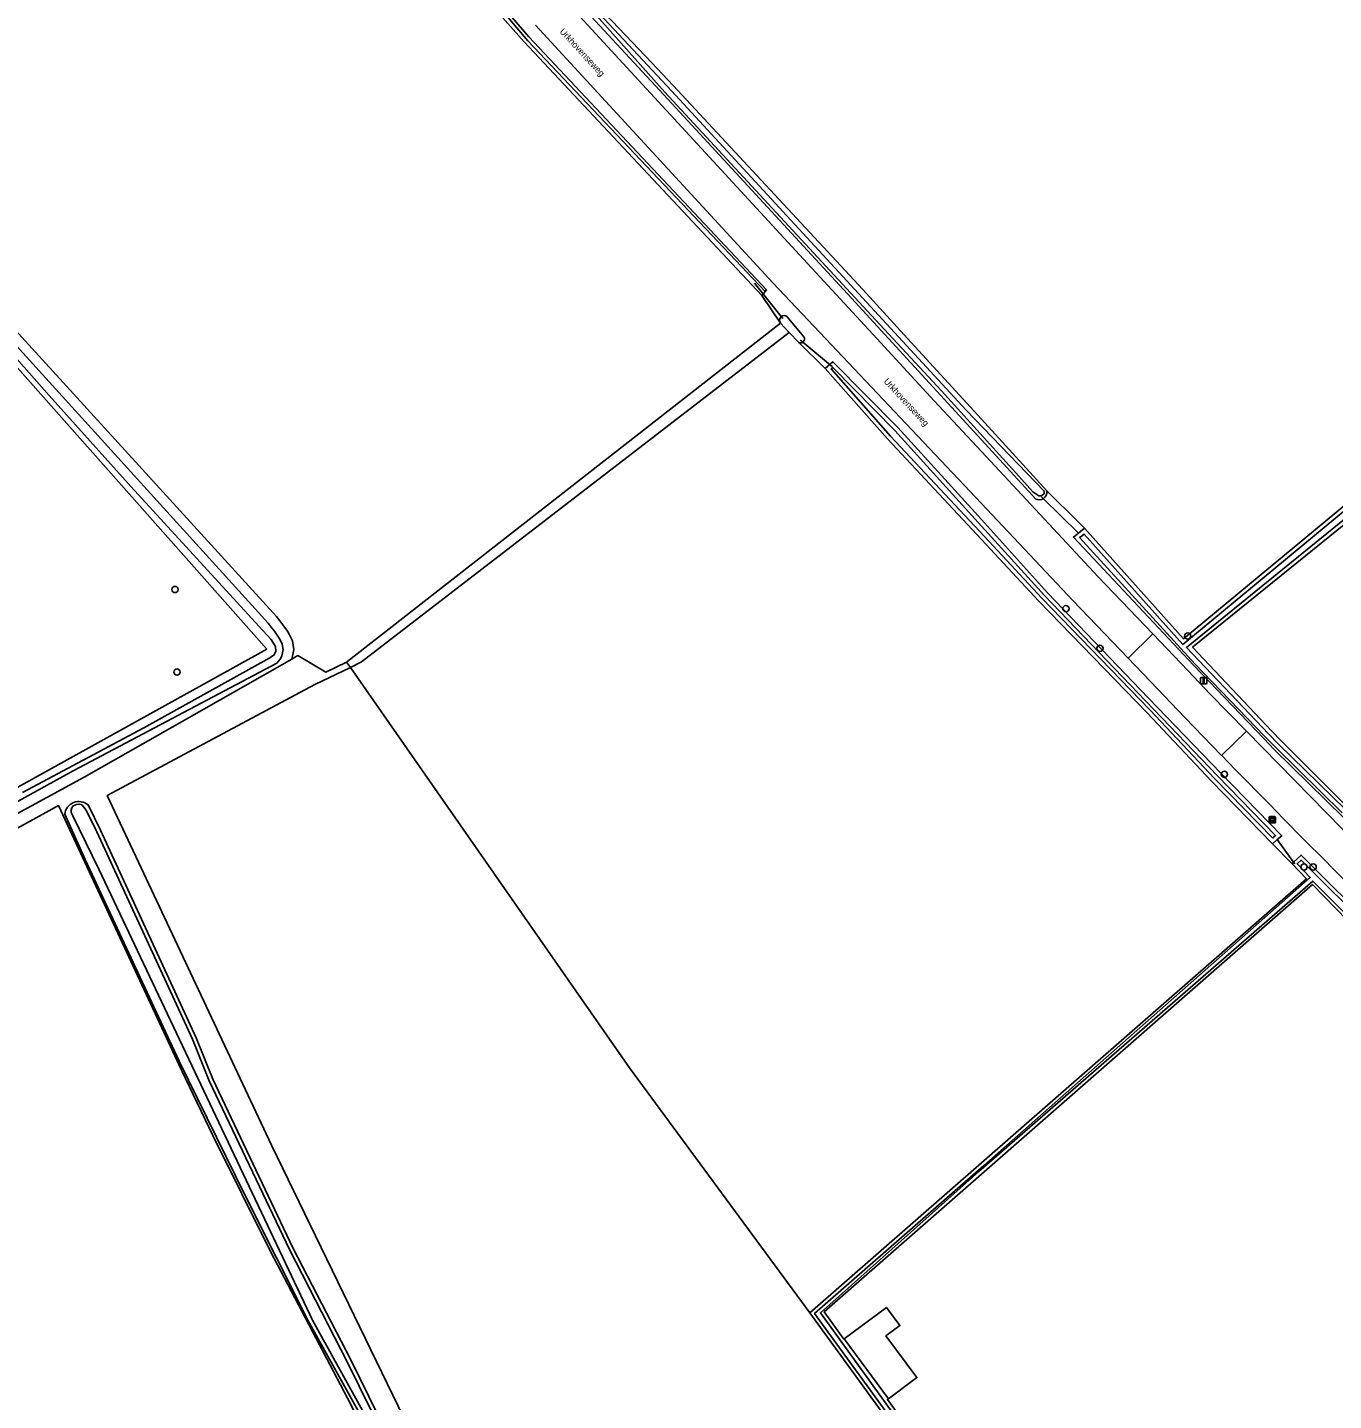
# Model space of a CAD drawing. Extents: x 164494 to 166241, y 382475 to 384495.
# Drawn here: x 165350.9 to 165555, y 382584 to 382798.6 of the extents above; entities that cross this region are included whole.
import ezdxf

# ---------------------------------------------------------------- set-up
doc = ezdxf.new("R2010")
doc.units = 0
for name, color, linetype in [('IMGEO_Boom', 7, 'Continuous'), ('IMGEO_Bouwland', 7, 'Continuous'), ('IMGEO_Duiker', 7, 'Continuous'), ('IMGEO_Erf', 7, 'Continuous'), ('IMGEO_Grasland_agrarisch', 7, 'Continuous'), ('IMGEO_Grasland_overig', 7, 'Continuous'), ('IMGEO_Groenvoorziening', 7, 'Continuous'), ('IMGEO_Hek', 7, 'Continuous'), ('IMGEO_Lichtmast', 7, 'Continuous'), ('IMGEO_Oever', 7, 'Continuous'), ('IMGEO_Openbare_ruimte_label', 7, 'Continuous'), ('IMGEO_Pand', 7, 'Continuous'), ('IMGEO_Rijbaan_lokaal_gesloten', 7, 'Continuous'), ('IMGEO_Rijbaan_lokaal_open', 7, 'Continuous'), ('IMGEO_Waterloop', 7, 'Continuous'), ('IMGEO_Wegwijzer', 7, 'Continuous')]:
    doc.layers.add(name, color=color, linetype=linetype)

msp = doc.modelspace()

# ---------------------------------------------------------------- linework, layer by layer
at = {"layer": 'IMGEO_Boom'}
for centre in [(165373.99, 382710.77), (165513.21, 382707.77), (165532.25, 382703.5), (165518.53, 382701.58), (165374.3, 382697.87), (165537.99, 382681.88), (165550.43, 382667.4), (165551.85, 382667.4)]:
    msp.add_circle(centre, 0.489, dxfattribs=at)
at = {"layer": 'IMGEO_Bouwland'}
msp.add_lwpolyline([(165439.25, 382802.82), (165448.48, 382793.1), (165451.85, 382789.55), (165481.46, 382757.64), (165488.44, 382750), (165500, 382737.37), (165510.24, 382726.17), (165515.2, 382721.28), (165516.13, 382720.35), (165531.58, 382703.08), (165565.88, 382731.47)], dxfattribs=at)
msp.add_lwpolyline([(165550.83, 382665.58), (165548.56, 382667.91), (165545.51, 382671.03), (165535.96, 382680.81), (165525.91, 382691.48), (165509, 382708.97), (165500, 382718.6), (165485.31, 382734.31), (165475.61, 382745.32), (165471.45, 382749.36), (165469.96, 382750.93), (165403.15, 382699.48), (165401.4, 382698.58), (165395.82, 382695.91), (165363.39, 382678.56), (165389.07, 382623.94), (165409.74, 382581.31), (165430.57, 382542.15), (165486.94, 382570.53), (165487.49, 382569.52), (165491.84, 382572.06), (165491.59, 382572.41), (165473.19, 382597.73), (165500, 382621.16)], close=True, dxfattribs=at)
at = {"layer": 'IMGEO_Duiker'}
for points in [[(165464.55, 382758.66), (165468.72, 382753.42), (165468.98, 382753.1)], [(165476.73, 382745.56), (165472.09, 382749.41), (165471.71, 382749.73)], [(165509.39, 382725.23), (165509.65, 382724.97), (165515.18, 382719.58)], [(165548.98, 382667.89), (165548.8, 382668.14), (165546.24, 382671.72)]]:
    msp.add_lwpolyline(points, dxfattribs=at)
at = {"layer": 'IMGEO_Erf'}
msp.add_lwpolyline([(165575.78, 382640.1), (165568.63, 382646.88), (165567.19, 382648.47), (165564.24, 382651.72), (165562.6, 382653.53), (165551.73, 382664.66), (165500, 382619.38), (165475.44, 382597.88), (165478.51, 382593.62), (165478.55, 382593.65), (165485.17, 382598.57), (165487.27, 382595.74), (165485.09, 382594.13), (165489.93, 382587.61), (165485.48, 382584.31), (165485.32, 382584.19), (165500, 382563.85), (165507.33, 382553.7), (165522.62, 382530.99), (165636.94, 382574.99), (165625.79, 382586.73)], close=True, dxfattribs=at)
at = {"layer": 'IMGEO_Grasland_agrarisch'}
for points in [[(165326.88, 382775.58), (165389.84, 382706.54), (165390.34, 382705.9), (165390.85, 382705.23), (165391.54, 382704.25), (165391.87, 382703.71), (165392.32, 382702.73), (165392.56, 382701.39), (165392.51, 382701.16), (165392.23, 382699.91), (165393.17, 382700.44), (165397.53, 382697.87), (165400.77, 382699.42), (165468.6, 382752.37), (165465.7, 382756.73), (165428.53, 382796.36), (165417.05, 382809.34)], [(165322.04, 382664.7), (165388.32, 382701.46), (165345.24, 382750)], [(165569.4, 382731.21), (165533.02, 382701.74), (165545.33, 382688.67), (165546.89, 382687.08), (165557.68, 382676.28)]]:
    msp.add_lwpolyline(points, dxfattribs=at)
msp.add_lwpolyline([(165425.5, 382538.24), (165418.91, 382549.58), (165416.19, 382554.47), (165400.96, 382584.41), (165388.9, 382607.3), (165379.91, 382625.45), (165374.99, 382635.66), (165355.79, 382676.99), (165231.39, 382608.37), (165248.77, 382587.82), (165257.29, 382578.44), (165262.78, 382578.65), (165266.56, 382578.95), (165266.59, 382574.97), (165262.47, 382574.93), (165261.94, 382573.12), (165270.16, 382563.93), (165272.43, 382562.04), (165323.58, 382553.4), (165367.77, 382546.66)], close=True, dxfattribs=at)
at = {"layer": 'IMGEO_Grasland_overig'}
msp.add_lwpolyline([(165469.96, 382750.93), (165468.6, 382752.37), (165400.77, 382699.42), (165401.4, 382698.58), (165403.15, 382699.48)], close=True, dxfattribs=at)
for points in [[(165409.74, 382581.31), (165389.07, 382623.94), (165363.39, 382678.56), (165395.82, 382695.91), (165401.4, 382698.58), (165400.77, 382699.42), (165397.53, 382697.87), (165393.17, 382700.44), (165392.23, 382699.91), (165359.77, 382681.45), (165231.84, 382611.82)], [(165231.39, 382608.37), (165355.79, 382676.99), (165374.99, 382635.66), (165379.91, 382625.45), (165388.9, 382607.3), (165400.96, 382584.41), (165416.19, 382554.47), (165418.91, 382549.58), (165425.5, 382538.24), (165425.65, 382537.98)], [(165360.39, 382677.12), (165362.32, 382673.14), (165377.27, 382640.73), (165379.87, 382634.24), (165392.42, 382607.91), (165401.45, 382590.37), (165407.08, 382578.94)], [(165425.65, 382537.98), (165425.85, 382537.95), (165411.41, 382565.13), (165405.97, 382576.33), (165394.76, 382596.6), (165384.84, 382616.27), (165374.62, 382637.08), (165359.94, 382668.57), (165356.74, 382675.64)]]:
    msp.add_lwpolyline(points, dxfattribs=at)
msp.add_arc((165358.97, 382675.4), 2.24, 50.2349, 173.7785, dxfattribs=at)
at = {"layer": 'IMGEO_Groenvoorziening'}
for points in [[(165418.01, 382810.21), (165429.3, 382797.15), (165466.42, 382757.59), (165466.19, 382757.33), (165465.7, 382756.73), (165468.6, 382752.37)], [(165434.78, 382803), (165472.18, 382762.41), (165483.64, 382750), (165492.61, 382740.28), (165500, 382732.35), (165518.27, 382712.76), (165526.78, 382703.83), (165532.31, 382698.04), (165535.71, 382694.46), (165541.43, 382688.62), (165558.9, 382670.83)], [(165508.51, 382724.91), (165500, 382734.18), (165485.49, 382750), (165479.7, 382756.3), (165450.37, 382788.09), (165437.67, 382801.8)], [(165537.54, 382684.85), (165534.68, 382687.81), (165531.82, 382690.77), (165526.41, 382696.39), (165522.95, 382700.02), (165514.32, 382709.07), (165500, 382724.22), (165488.23, 382736.66), (165475.63, 382750), (165467.41, 382758.71), (165430.31, 382798.95)], [(165469.63, 382753.39), (165472.27, 382750.27)], [(165471.45, 382749.36), (165475.61, 382745.32), (165476.8, 382746.34), (165486.97, 382736.07), (165500, 382721.69), (165510.36, 382710.25), (165526.14, 382693.78), (165537.4, 382682.09), (165546.95, 382672.27), (165546.24, 382671.72), (165545.51, 382671.03), (165548.56, 382667.91), (165548.8, 382668.14), (165549.96, 382669.28), (165553.27, 382665.99), (165563.92, 382655.38), (165562.6, 382653.53), (165564.24, 382651.72), (165565.6, 382656.4), (165555.54, 382666.56), (165555.17, 382666.93), (165554.8, 382667.3)], [(165556.62, 382675.15), (165545.78, 382685.78), (165544.17, 382687.49), (165533.15, 382698.96), (165514.39, 382718.95), (165515.18, 382719.58), (165516.13, 382720.35), (165515.2, 382721.28), (165510.24, 382726.17)]]:
    msp.add_lwpolyline(points, dxfattribs=at)
for centre, radius, start, end in [((165469.31, 382752.82), 0.84, 133.9502, 212.3086), ((165469.16, 382752.84), 0.728, 49.5124, 126.5725), ((165471.73, 382749.93), 0.64, 305.1433, 32.0582), ((165471.72, 382749.98), 0.685, 246.0377, 302.7732), ((165509.03, 382726.01), 1.22, 244.3295, 300.749), ((165509.03, 382726.01), 1.22, 300.764, 7.4823), ((166862.27, 383970.43), 1845.97, 224.14065, 224.9045)]:
    msp.add_arc(centre, radius, start, end, dxfattribs=at)
at = {"layer": 'IMGEO_Hek'}
for points in [[(165395.82, 382695.91), (165401.4, 382698.58)], [(165401.4, 382698.58), (165445, 382636.04), (165473.19, 382597.73)], [(165363.39, 382678.56), (165395.82, 382695.91)], [(165231.39, 382608.37), (165355.79, 382676.99), (165374.99, 382635.66), (165379.91, 382625.45), (165388.9, 382607.3), (165400.96, 382584.41)], [(165400.96, 382584.41), (165416.19, 382554.47), (165418.91, 382549.58), (165425.5, 382538.24)]]:
    msp.add_lwpolyline(points, dxfattribs=at)
at = {"layer": 'IMGEO_Lichtmast'}
for p, q in [((165534.25, 382696.11), (165534.25, 382696.91)), ((165534.25, 382696.91), (165534.25, 382696.11)), ((165534.35, 382697.01), (165535.14, 382697.01)), ((165535.14, 382697.01), (165534.35, 382697.01)), ((165535.24, 382696.91), (165535.24, 382696.11)), ((165535.24, 382696.11), (165535.24, 382696.91)), ((165535.14, 382696.01), (165534.35, 382696.01)), ((165534.35, 382696.01), (165535.14, 382696.01))]:
    msp.add_line(p, q, dxfattribs=at)
msp.add_lwpolyline([(165534.67, 382696.88), (165534.82, 382696.88), (165534.82, 382696.13), (165534.67, 382696.13), (165534.67, 382696.88)], dxfattribs=at)
for centre, start, end in [((165534.35, 382696.91), 90, 180), ((165534.35, 382696.91), 90, 180), ((165535.14, 382696.91), 0, 90), ((165535.14, 382696.91), 360, 90), ((165534.35, 382696.11), 180, 270), ((165534.35, 382696.11), 180, 270), ((165535.14, 382696.11), 270, 0), ((165535.14, 382696.11), 270, 0)]:
    msp.add_arc(centre, 0.1, start, end, dxfattribs=at)
at = {"layer": 'IMGEO_Oever'}
for points in [[(165429.3, 382797.15), (165418.01, 382810.21), (165410.83, 382819.51), (165399.13, 382836.22), (165397.77, 382835.43), (165399.37, 382833.21), (165401.49, 382831.69), (165412.14, 382816.6), (165429.14, 382796.5), (165466.19, 382757.33), (165466.42, 382757.59)], [(165431.73, 382809.62), (165427.8, 382814.18), (165427.69, 382814.47), (165427.7, 382814.71), (165427.82, 382814.87), (165427.99, 382814.96), (165428.26, 382814.91), (165428.83, 382814.39), (165433.61, 382808.38), (165438.86, 382802.32), (165451.56, 382788.71), (165497.61, 382738.81), (165509.82, 382726.14), (165509.82, 382725.77), (165509.4, 382725.41), (165508.99, 382725.41), (165508.04, 382726.01), (165505.84, 382728.49), (165493.77, 382741.81), (165483.46, 382752.93), (165450.54, 382788.48)], [(165510.36, 382710.25), (165500, 382721.69), (165486.97, 382736.07), (165476.8, 382746.34), (165475.61, 382745.32), (165485.31, 382734.31), (165500, 382718.6), (165509, 382708.97), (165525.91, 382691.48), (165535.96, 382680.81), (165545.51, 382671.03), (165546.24, 382671.72), (165546.95, 382672.27), (165537.4, 382682.09), (165526.14, 382693.78)], [(165485.78, 382734.74), (165476.52, 382745.25), (165476.77, 382745.46), (165486.5, 382735.63), (165499.52, 382721.26), (165509.89, 382709.81), (165525.68, 382693.34), (165536.93, 382681.65), (165545.99, 382672.34), (165545.82, 382672.2), (165545.53, 382671.93), (165536.42, 382681.26), (165526.38, 382691.92), (165509.46, 382709.42), (165500.47, 382719.04)]]:
    msp.add_lwpolyline(points, close=True, dxfattribs=at)
for points in [[(165451.85, 382789.55), (165448.48, 382793.1), (165439.25, 382802.82), (165428.7, 382815.63), (165427.13, 382814.77), (165437.67, 382801.8), (165450.37, 382788.09), (165479.7, 382756.3), (165485.49, 382750), (165500, 382734.18), (165508.51, 382724.91)], [(165510.24, 382726.17), (165500, 382737.37), (165488.44, 382750), (165481.46, 382757.64), (165451.85, 382789.55)], [(165231.84, 382611.82), (165359.77, 382681.45), (165392.23, 382699.91), (165392.51, 382701.16), (165392.56, 382701.39), (165392.32, 382702.73), (165391.87, 382703.71), (165391.54, 382704.25), (165390.85, 382705.23), (165390.34, 382705.9), (165389.84, 382706.54), (165326.88, 382775.58)], [(165350.14, 382679.06), (165369.12, 382689.16), (165388.78, 382700.08), (165389.48, 382700.54), (165389.74, 382701.12), (165389.67, 382701.84), (165389.02, 382702.95), (165387.06, 382705.03), (165367.15, 382726.82), (165354.34, 382741.08), (165328.5, 382770.3)], [(165348.17, 382750), (165388.54, 382705.53), (165389.03, 382704.9), (165389.52, 382704.26), (165390.16, 382703.34), (165390.41, 382702.93), (165390.73, 382702.23), (165390.89, 382701.39), (165390.7, 382700.34), (165390.42, 382699.88), (165389.88, 382699.28), (165358.08, 382682.43), (165309.58, 382655.69)], [(165345.24, 382750), (165388.32, 382701.46), (165322.04, 382664.7)], [(165565.88, 382731.47), (165531.58, 382703.08), (165516.13, 382720.35), (165515.18, 382719.58), (165514.39, 382718.95), (165533.15, 382698.96), (165544.17, 382687.49), (165545.78, 382685.78), (165556.62, 382675.15)], [(165556.39, 382675.86), (165546.03, 382686.08), (165544.26, 382687.85), (165533.38, 382699.18), (165515.36, 382718.88), (165515.6, 382719.07), (165516.06, 382719.44), (165531.51, 382702.16), (165566.3, 382730.96)], [(165568.98, 382731.73), (165532.05, 382701.69), (165544.85, 382688.22), (165546.42, 382686.62), (165556.9, 382676.38)], [(165557.68, 382676.28), (165546.89, 382687.08), (165545.33, 382688.67), (165533.02, 382701.74), (165569.4, 382731.21)], [(165406.52, 382576.62), (165395.53, 382596.49), (165373.3, 382643.41), (165362.09, 382667.08), (165358.04, 382675.38), (165357.74, 382675.93), (165357.77, 382676.29), (165357.84, 382676.64), (165358.08, 382676.94), (165358.57, 382677.16), (165358.97, 382677.23), (165359.3, 382677.16), (165359.54, 382677.04), (165359.96, 382676.49), (165360.21, 382676.09), (165361.76, 382672.88), (165376.7, 382640.48), (165379.3, 382633.99), (165391.87, 382607.64), (165400.89, 382590.09), (165406.52, 382578.67)], [(165414.66, 382563.28), (165411.38, 382569.62), (165407.08, 382578.94), (165401.45, 382590.37), (165392.42, 382607.91), (165379.87, 382634.24), (165377.27, 382640.73), (165362.32, 382673.14), (165360.39, 382677.12)], [(165356.74, 382675.64), (165359.94, 382668.57), (165374.62, 382637.08), (165384.84, 382616.27), (165394.76, 382596.6), (165405.97, 382576.33), (165411.41, 382565.13), (165425.85, 382537.95), (165425.65, 382537.98), (165401.14, 382541.58), (165385.32, 382543.79), (165351.2, 382548.95), (165342.55, 382550.34)], [(165563.92, 382655.38), (165553.27, 382665.99), (165549.96, 382669.28), (165548.8, 382668.14), (165548.56, 382667.91), (165550.83, 382665.58), (165500, 382621.16), (165473.19, 382597.73), (165491.59, 382572.41), (165491.84, 382572.06), (165492.23, 382571.52), (165500, 382560.82), (165504.29, 382554.91), (165521.83, 382528.01), (165525.31, 382523.18), (165527.17, 382520.62), (165529.5, 382519.54), (165543.3, 382517.85), (165561.7, 382516.18)], [(165559.2, 382519.02), (165538.06, 382520.26), (165529.61, 382520.81), (165528.05, 382521.54), (165524.02, 382525.73), (165522.29, 382528.32), (165504.75, 382555.23), (165500.45, 382561.15), (165492.69, 382571.84), (165492.29, 382572.39), (165492.04, 382572.73), (165473.94, 382597.64), (165500.37, 382620.74), (165551.39, 382665.75), (165549.35, 382667.9), (165549.96, 382668.49), (165552.87, 382665.59), (165563.19, 382655.32)], [(165562.53, 382654.39), (165551.8, 382665.21), (165499.63, 382619.8), (165474.85, 382597.75), (165499.55, 382563.53), (165506.87, 382553.38), (165522.28, 382529.91), (165523, 382530.24), (165636.32, 382572.77)], [(165636.94, 382574.99), (165522.62, 382530.99), (165507.33, 382553.7), (165500, 382563.85), (165485.32, 382584.19), (165485.48, 382584.31), (165478.55, 382593.65), (165478.51, 382593.62), (165475.44, 382597.88), (165500, 382619.38), (165551.73, 382664.66), (165562.6, 382653.53)]]:
    msp.add_lwpolyline(points, dxfattribs=at)
for centre, radius, start, end in [((165509.03, 382726.01), 1.22, 244.3295, 300.749), ((165509.03, 382726.01), 1.22, 300.764, 7.4823), ((165358.97, 382675.4), 2.24, 50.2349, 173.7785)]:
    msp.add_arc(centre, radius, start, end, dxfattribs=at)
at = {"layer": 'IMGEO_Pand'}
msp.add_lwpolyline([(165485.17, 382598.57), (165478.55, 382593.65), (165485.48, 382584.31), (165489.93, 382587.61), (165485.09, 382594.13), (165487.27, 382595.74)], close=True, dxfattribs=at)
at = {"layer": 'IMGEO_Rijbaan_lokaal_gesloten'}
for points in [[(165619.42, 382610.4), (165611.85, 382617.98), (165575.84, 382653.73), (165559.16, 382670.56), (165558.9, 382670.83), (165541.43, 382688.62), (165537.54, 382684.85)], [(165554.8, 382667.3), (165555.17, 382666.93), (165555.54, 382666.56), (165565.6, 382656.4), (165572, 382649.98), (165608.7, 382613.27), (165658.65, 382562.86), (165681.33, 382539.89), (165681.97, 382538.86), (165685.49, 382533.22), (165686.15, 382532.15), (165686.33, 382532.25), (165692.71, 382535.26), (165692.92, 382535.35), (165687.52, 382541.74), (165681.89, 382548.18), (165677.65, 382552.37), (165663.07, 382566.68), (165619.42, 382610.4)]]:
    msp.add_lwpolyline(points, dxfattribs=at)
msp.add_arc((166862.27, 383970.43), 1845.97, 224.14065, 224.9045, dxfattribs=at)
at = {"layer": 'IMGEO_Rijbaan_lokaal_open'}
msp.add_lwpolyline([(165430.31, 382798.95), (165467.41, 382758.71), (165475.63, 382750), (165488.23, 382736.66), (165500, 382724.22), (165514.32, 382709.07), (165522.95, 382700.02), (165526.78, 382703.83), (165518.27, 382712.76), (165500, 382732.35), (165492.61, 382740.28), (165483.64, 382750), (165472.18, 382762.41), (165434.78, 382803)], dxfattribs=at)
msp.add_lwpolyline([(165531.82, 382690.77), (165534.68, 382687.81), (165537.54, 382684.85), (165541.43, 382688.62), (165535.71, 382694.46), (165532.31, 382698.04), (165526.78, 382703.83), (165522.95, 382700.02), (165526.41, 382696.39)], close=True, dxfattribs=at)
at = {"layer": 'IMGEO_Waterloop'}
for points in [[(165399.37, 382833.21), (165409.9, 382818.62), (165417.05, 382809.34), (165428.53, 382796.36), (165465.7, 382756.73), (165466.19, 382757.33), (165429.14, 382796.5), (165412.14, 382816.6), (165401.49, 382831.69)], [(165431.73, 382809.62), (165450.54, 382788.48), (165483.46, 382752.93), (165493.77, 382741.81), (165505.84, 382728.49), (165508.04, 382726.01), (165508.99, 382725.41), (165509.4, 382725.41), (165509.82, 382725.77), (165509.82, 382726.14), (165497.61, 382738.81), (165451.56, 382788.71), (165438.86, 382802.32), (165433.61, 382808.38), (165428.83, 382814.39), (165428.26, 382814.91), (165427.99, 382814.96), (165427.82, 382814.87), (165427.7, 382814.71), (165427.69, 382814.47), (165427.8, 382814.18)], [(165485.78, 382734.74), (165500.47, 382719.04), (165509.46, 382709.42), (165526.38, 382691.92), (165536.42, 382681.26), (165545.53, 382671.93), (165545.82, 382672.2), (165545.99, 382672.34), (165536.93, 382681.65), (165525.68, 382693.34), (165509.89, 382709.81), (165499.52, 382721.26), (165486.5, 382735.63), (165476.77, 382745.46), (165476.52, 382745.25)]]:
    msp.add_lwpolyline(points, close=True, dxfattribs=at)
for points in [[(165328.5, 382770.3), (165354.34, 382741.08), (165367.15, 382726.82), (165387.06, 382705.03), (165389.02, 382702.95), (165389.67, 382701.84), (165389.74, 382701.12), (165389.48, 382700.54), (165388.78, 382700.08), (165369.12, 382689.16), (165350.14, 382679.06)], [(165468.6, 382752.37), (165469.96, 382750.93), (165471.45, 382749.36)], [(165472.27, 382750.27), (165469.63, 382753.39)], [(165309.58, 382655.69), (165358.08, 382682.43), (165389.88, 382699.28), (165390.42, 382699.88), (165390.7, 382700.34), (165390.89, 382701.39), (165390.73, 382702.23), (165390.41, 382702.93), (165390.16, 382703.34), (165389.52, 382704.26), (165389.03, 382704.9), (165388.54, 382705.53), (165348.17, 382750)], [(165566.3, 382730.96), (165531.51, 382702.16), (165516.06, 382719.44), (165515.6, 382719.07), (165515.36, 382718.88), (165533.38, 382699.18), (165544.26, 382687.85), (165546.03, 382686.08), (165556.39, 382675.86)], [(165556.9, 382676.38), (165546.42, 382686.62), (165544.85, 382688.22), (165532.05, 382701.69), (165568.98, 382731.73)], [(165406.52, 382578.67), (165400.89, 382590.09), (165391.87, 382607.64), (165379.3, 382633.99), (165376.7, 382640.48), (165361.76, 382672.88), (165360.21, 382676.09), (165359.96, 382676.49), (165359.54, 382677.04), (165359.3, 382677.16), (165358.97, 382677.23), (165358.57, 382677.16), (165358.08, 382676.94), (165357.84, 382676.64), (165357.77, 382676.29), (165357.74, 382675.93), (165358.04, 382675.38), (165362.09, 382667.08), (165373.3, 382643.41), (165395.53, 382596.49), (165406.52, 382576.62)], [(165563.19, 382655.32), (165552.87, 382665.59), (165549.96, 382668.49), (165549.35, 382667.9), (165551.39, 382665.75), (165500.37, 382620.74), (165473.94, 382597.64), (165492.04, 382572.73), (165492.29, 382572.39), (165492.69, 382571.84), (165500.45, 382561.15), (165504.75, 382555.23), (165522.29, 382528.32), (165524.02, 382525.73), (165528.05, 382521.54), (165529.61, 382520.81), (165538.06, 382520.26), (165559.2, 382519.02)], [(165636.32, 382572.77), (165523, 382530.24), (165522.28, 382529.91), (165506.87, 382553.38), (165499.55, 382563.53), (165474.85, 382597.75), (165499.63, 382619.8), (165551.8, 382665.21), (165562.53, 382654.39)]]:
    msp.add_lwpolyline(points, dxfattribs=at)
for centre, radius, start, end in [((165469.31, 382752.82), 0.84, 133.9502, 212.3086), ((165469.16, 382752.84), 0.728, 49.5124, 126.5725), ((165471.73, 382749.93), 0.64, 305.1433, 32.0582), ((165471.72, 382749.98), 0.685, 246.0377, 302.7732)]:
    msp.add_arc(centre, radius, start, end, dxfattribs=at)
at = {"layer": 'IMGEO_Wegwijzer'}
for p, q in [((165544.98, 382674.39), (165544.98, 382675.18)), ((165544.98, 382675.18), (165544.98, 382674.39)), ((165545.08, 382675.28), (165545.87, 382675.28)), ((165545.87, 382675.28), (165545.08, 382675.28)), ((165545.97, 382675.18), (165545.97, 382674.39)), ((165545.97, 382674.39), (165545.97, 382675.18)), ((165545.87, 382674.29), (165545.08, 382674.29)), ((165545.08, 382674.29), (165545.87, 382674.29))]:
    msp.add_line(p, q, dxfattribs=at)
for points in [[(165545.09, 382675.02), (165545.87, 382675.02), (165545.87, 382674.55), (165545.09, 382674.55), (165545.09, 382675.02)], [(165545.15, 382674.95), (165545.15, 382674.62), (165545.81, 382674.62), (165545.81, 382674.95), (165545.15, 382674.95)]]:
    msp.add_lwpolyline(points, dxfattribs=at)
for centre, start, end in [((165545.08, 382675.18), 90, 180), ((165545.08, 382675.18), 90, 180), ((165545.87, 382675.18), 0, 90), ((165545.87, 382675.18), 360, 90), ((165545.08, 382674.39), 180, 270), ((165545.08, 382674.39), 180, 270), ((165545.87, 382674.39), 270, 0), ((165545.87, 382674.39), 270, 0)]:
    msp.add_arc(centre, 0.1, start, end, dxfattribs=at)

# ---------------------------------------------------------------- texts
at = {"layer": 'IMGEO_Openbare_ruimte_label'}
for rotation, p in [(312.69, (165434.02, 382797.9)), (312.9329, (165484.66, 382743.22))]:
    msp.add_text('Urkhovenseweg', height=1, rotation=rotation, dxfattribs=at).set_placement(p)

doc.saveas('drawing.dxf')
